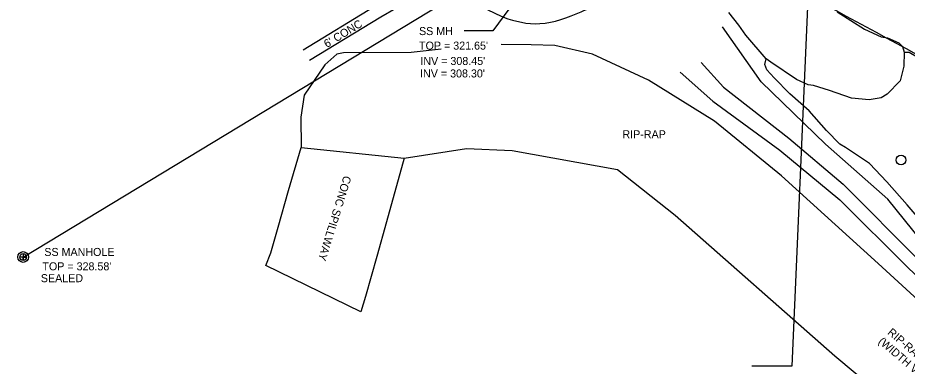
# Model space of a CAD drawing. Extents: x 2057786 to 2059508, y 687766 to 689280.
# Drawn here: x 2058050.7 to 2058495.3, y 688810.6 to 688984.5 of the extents above; entities that cross this region are included whole.
import ezdxf

# ---------------------------------------------------------------- set-up
doc = ezdxf.new("R2010")
doc.units = 0
for name, color, linetype in [('Exist Right of Way Line', 7, 'Continuous'), ('Exist Roads EOP', 7, 'Continuous'), ('Exist Roads EOP Other', 7, 'Continuous'), ('Exist Roads EOP Text', 7, 'Continuous'), ('Exist Roads Soil', 7, 'Continuous'), ('Exist Utilities Other Pole CELL', 7, 'Continuous'), ('Exist Utilities Sanitary Sewer Manhole CELL', 7, 'Continuous'), ('Exist Utilities Sanitary Sewer Manhole Leader', 7, 'Continuous'), ('Exist Utilities Sanitary Sewer Manhole Text', 7, 'Continuous'), ('Exist Utilities Sanitary Sewer Manhole Top Elevation', 7, 'Continuous'), ('Exist Utilities Sanitary Sewer UG Line', 7, 'Continuous'), ('Exist Utilities Sanitary Sewer UG Line Invert Elevation', 7, 'Continuous'), ('Exist Utilities Water Valve Leader', 7, 'Continuous'), ('Old_Level_11', 7, 'Continuous'), ('Old_Level_28', 7, 'Continuous'), ('Old_Level_8', 7, 'Continuous')]:
    doc.layers.add(name, color=color, linetype=linetype)

# ---------------------------------------------------------------- blocks, each defined once
blk = doc.blocks.new('EXIST UTILITIES OTHER POLE')
at = {"layer": 'Exist Utilities Other Pole CELL'}
blk.add_circle((0, 0), 0.0493, dxfattribs=at)

msp = doc.modelspace()

# ---------------------------------------------------------------- linework, layer by layer
at = {"layer": 'Exist Right of Way Line'}
msp.add_arc((2055622.73, 683696.35), 6004.25, 60.769843, 62.505867, dxfattribs=at)
at = {"layer": 'Exist Roads EOP'}
msp.add_lwpolyline([(2058273.09, 689001.9), (2058265.37, 689006.55), (2058260.68, 689009.29), (2058228.92, 688990.01), (2058193.4, 688968.41)], dxfattribs=at)
msp.add_spline([(2058790.44, 688783.33), (2058774.52, 688799.91), (2058750.56, 688821.57), (2058724.88, 688843.53), (2058697.06, 688865.63), (2058669.08, 688886.89), (2058642.64, 688905.34), (2058608.82, 688927.02), (2058574.14, 688948.51), (2058534.92, 688970.39), (2058490.85, 688994.7)], degree=3, dxfattribs=at)
at = {"layer": 'Exist Roads EOP Other'}
msp.add_lwpolyline([(2058196.59, 688963.42), (2058232.13, 688984.97), (2058254.7, 688998.23)], dxfattribs=at)
msp.add_spline([(2058254.7, 688998.23), (2058259.03, 689000.39), (2058261.61, 689000.49), (2058265.31, 688999.4), (2058293.55, 688984.91), (2058311.62, 688981.63), (2058332.29, 688987.58), (2058343.11, 688992.31), (2058367.43, 689004.12), (2058388.89, 689018.98)], degree=3, dxfattribs=at)
at = {"layer": 'Exist Roads Soil'}
for points in [[(2058392.23, 688962.26), (2058403.46, 688949.91), (2058436.05, 688924.4), (2058463.33, 688901.57), (2058501.42, 688863.21), (2058528.5, 688838.55), (2058566.54, 688802.58), (2058595.96, 688784), (2058631.65, 688776.32), (2058672.35, 688770.1)], [(2058381.8, 688957.42), (2058398.21, 688943), (2058431.63, 688918.41), (2058461.61, 688893.72), (2058495.76, 688859.78), (2058526.85, 688830.27), (2058560.88, 688799.23), (2058594.24, 688776.2), (2058631.79, 688769.37), (2058672.86, 688764.1)]]:
    msp.add_lwpolyline(points, dxfattribs=at)
at = {"layer": 'Exist Utilities Sanitary Sewer Manhole CELL'}
msp.add_lwpolyline([(2058053.44, 688866.86), (2058053.44, 688863.43), (2058053.44, 688865.14), (2058055.15, 688865.14), (2058051.73, 688865.14)], dxfattribs=at)
for radius in [2.69, 1.71]:
    msp.add_circle((2058053.44, 688865.14), radius, dxfattribs=at)
at = {"layer": 'Exist Utilities Sanitary Sewer Manhole Leader'}
msp.add_lwpolyline([(2058325, 689027.94), (2058288.11, 688978.04), (2058273.77, 688978.04)], dxfattribs=at)
at = {"layer": 'Exist Utilities Sanitary Sewer UG Line'}
msp.add_lwpolyline([(2058053.44, 688865.14), (2058325.58, 689029.75)], dxfattribs=at)
at = {"layer": 'Exist Utilities Water Valve Leader'}
msp.add_lwpolyline([(2058445.44, 688990.05), (2058437.58, 688810.66), (2058417.57, 688810.66)], dxfattribs=at)
at = {"layer": 'Old_Level_11'}
for points in [[(2058460.3, 688987.45), (2058474.02, 688978.94), (2058482.27, 688975.07), (2058485.36, 688974.59), (2058491.06, 688972.06), (2058492.87, 688970.25), (2058493.72, 688967.38), (2058493.53, 688960.34), (2058491.81, 688953.08), (2058485.3, 688946.5), (2058482.27, 688944.55), (2058476.28, 688943.58), (2058467.37, 688944.38), (2058456.51, 688948.2), (2058448.5, 688950.77), (2058445.8, 688951.02), (2058439.91, 688953.76), (2058427.11, 688962.32), (2058424.79, 688964.06), (2058414.68, 688975.8), (2058411.13, 688980.83), (2058406.05, 688987.15)], [(2058532.81, 688849.75), (2058531, 688851.57), (2058528.26, 688852.55), (2058521.3, 688857.59), (2058516.39, 688861.6), (2058512.82, 688866.23), (2058509.12, 688872.08), (2058504.26, 688880.72), (2058495.27, 688891.2), (2058485.13, 688902.75), (2058476.37, 688911.9), (2058464.41, 688919.73), (2058461.58, 688921.4), (2058455.02, 688928.31), (2058446.29, 688938.07), (2058436.58, 688946.55), (2058428.75, 688954.61), (2058425.15, 688958.63), (2058424.1, 688961.31), (2058424.79, 688964.06)], [(2058493.72, 688967.38), (2058496.23, 688967.34), (2058500.72, 688964.67), (2058505.57, 688961.38), (2058513.88, 688959.09), (2058515.82, 688956.29)]]:
    msp.add_lwpolyline(points, dxfattribs=at)
at = {"layer": 'Old_Level_8'}
msp.add_line((2058192.4, 688919.82), (2058243.89, 688914.56), dxfattribs=at)
for points in [[(2058710.76, 688777.94), (2058639.82, 688785.6), (2058579.89, 688802.35), (2058544.82, 688828.11), (2058510.55, 688863.02), (2058485.54, 688893.98), (2058454.38, 688921.53), (2058422.23, 688952.56), (2058403.03, 688979.97)], [(2058262.4, 688968.84), (2058247.4, 688967.16), (2058213.49, 688967.02), (2058210.14, 688966.31), (2058204.14, 688961.13), (2058193.89, 688945.9), (2058192.18, 688934.88), (2058192.4, 688919.82)], [(2058734.92, 688753.52), (2058735.51, 688760.64), (2058736.99, 688765.98), (2058740.85, 688771.33), (2058730.47, 688774.89), (2058710.76, 688777.94), (2058683.64, 688756.81), (2058647.8, 688760.5), (2058609.04, 688770.73), (2058573.94, 688781.35), (2058554.73, 688796.64), (2058518.83, 688827.17), (2058480.84, 688861.92), (2058432.5, 688905.71), (2058398.97, 688932.94), (2058365.98, 688953.37), (2058338.05, 688966.46), (2058319.19, 688970.72), (2058307.26, 688971.08), (2058292.32, 688971.2)], [(2058177.24, 688867.27), (2058180.9, 688879.97), (2058186.12, 688898.26), (2058192.4, 688919.82)], [(2058243.89, 688914.56), (2058274.94, 688919.33), (2058297.8, 688918.3), (2058350.46, 688908.85), (2058379.27, 688886.03), (2058459.18, 688815.88), (2058518.04, 688766.49), (2058546.6, 688746.07), (2058577.46, 688734.39), (2058606.33, 688729.69), (2058618.83, 688725.97), (2058623.23, 688723.41), (2058623.36, 688718.56), (2058621.09, 688706.79), (2058622.32, 688699.87), (2058624.31, 688695.72), (2058627.84, 688693.91), (2058629.3, 688692.92), (2058633.15, 688691.6), (2058635.7, 688693.01)], [(2058243.89, 688914.56), (2058235, 688882.76), (2058230.14, 688865.39), (2058224.51, 688845.51)], [(2058224.51, 688845.51), (2058222.23, 688837.81), (2058174.78, 688860.9), (2058177.24, 688867.27)]]:
    msp.add_lwpolyline(points, dxfattribs=at)

# ---------------------------------------------------------------- block references
at = {"layer": 'Exist Utilities Other Pole CELL', "xscale": 50, "yscale": 50}
msp.add_blockref('EXIST UTILITIES OTHER POLE', (2058492.19, 688913.54), dxfattribs=at)

# ---------------------------------------------------------------- texts
at = {"layer": 'Exist Roads EOP Text'}
msp.add_text("6' CONC", height=4, rotation=31.3169, dxfattribs=at).set_placement((2058205.24, 688969.42))
at = {"layer": 'Exist Utilities Sanitary Sewer Manhole Text'}
for s, p in [('SS MH', (2058251.29, 688975.91)), ('SS MANHOLE', (2058064.01, 688865.67))]:
    msp.add_text(s, height=4, rotation=0, dxfattribs=at).set_placement(p)
at = {"layer": 'Exist Utilities Sanitary Sewer Manhole Top Elevation'}
for s, p in [("TOP = 321.65'", (2058251.3, 688968.66)), ("TOP = 328.58'", (2058063.05, 688858.5))]:
    msp.add_text(s, height=4, rotation=0, dxfattribs=at).set_placement(p)
at = {"layer": 'Exist Utilities Sanitary Sewer UG Line Invert Elevation'}
for s, p in [("INV = 308.45'", (2058251.96, 688961)), ("INV = 308.30'", (2058251.81, 688954.77)), ('SEALED', (2058062.27, 688852.58))]:
    msp.add_text(s, height=4, rotation=0, dxfattribs=at).set_placement(p)
at = {"layer": 'Old_Level_28'}
msp.add_text('RIP-RAP', height=4, dxfattribs=at).set_placement((2058352.95, 688924.41))
for s, rotation, p in [('CONC SPILLWAY', 252.8556, (2058213.7, 688906.03)), ('RIP-RAP SPILLWAY', 319.3747, (2058485.15, 688826.99)), ('(WIDTH VARIES)', 319.3747, (2058480.51, 688822.51))]:
    msp.add_text(s, height=4, rotation=rotation, dxfattribs=at).set_placement(p)

doc.saveas('drawing.dxf')
